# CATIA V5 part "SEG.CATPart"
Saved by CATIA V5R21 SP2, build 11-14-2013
Part number: SEG
Bounding box of the stored display mesh (mm): x -10.275 to 10.275, y -10.275 to 10.275, z 0 to 101.592
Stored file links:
  C:\Users\Administrador\Desktop\SEG.CATPart
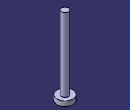
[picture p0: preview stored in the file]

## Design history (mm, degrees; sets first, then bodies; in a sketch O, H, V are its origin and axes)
AxisSystem1: origin (0, 0, 0), X (1, 0, 0), Y (0, 1, 0), Z (0, 0, 1)
Set1
  Sketch1 on YZ plane of AxisSystem1, origin (0, 0, 0), H (0, 1, 0), V (0, 0, 1)
    point P1 (0, 101.5923)
    line L1 (0, 101.5923) -> (4.5449, 101.5923)
    line L2 (4.5449, 101.5923) -> (4.5449, 6.3287)
    line L3 (4.5449, 6.3287) -> (10.2768, 6.3287)
    line L4 (10.2768, 6.3287) -> (10.2768, 0)
    point P5 (10.2768, 0)
    line L5 (10.2768, 0) -> (0, 0)
    coincidence: P1 V, P5 H
    horizontal: L1 H, L3 H, L5 H
    vertical: L2 V, L4 V
  Point1: (0, 0, 0), in AxisSystem1
Body1 (main body)
  Shaft1: profile Sketch1, axis Z axis, angle 360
